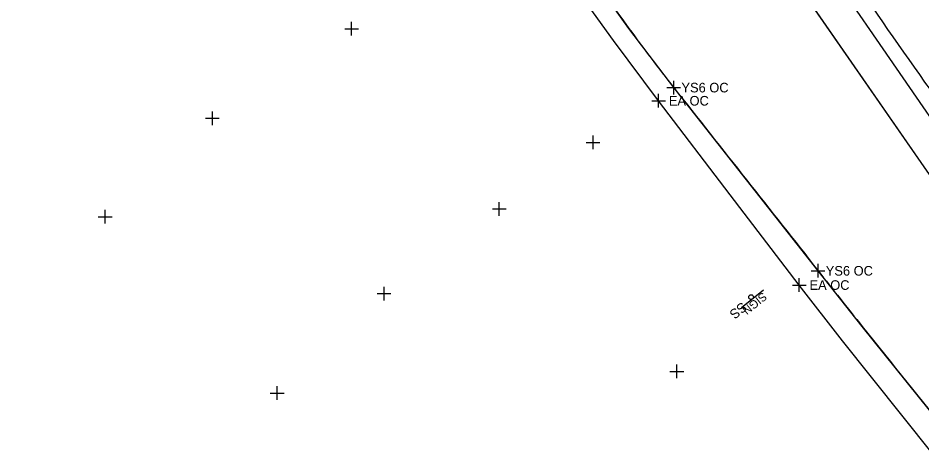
# Model space of a CAD drawing. Extents: x 1324236 to 1326110, y 459090 to 460782.
# Drawn here: x 1325451.1 to 1325582.8, y 459988.7 to 460050.8 of the extents above; entities that cross this region are included whole.
import ezdxf

# ---------------------------------------------------------------- set-up
doc = ezdxf.new("R2010")
doc.units = 0
for name, color, linetype in [('DR_X_Ditch', 7, 'Continuous'), ('DT_X_Contour_Minor', 7, 'Continuous'), ('DV_X_Property_Line', 7, 'Continuous'), ('LT_X_Poles', 7, 'Continuous'), ('PM_X_Edge_Line', 7, 'Continuous'), ('PM_X_Parking_Lot_Stall', 7, 'Continuous'), ('PV_X_Shoulder', 7, 'Continuous'), ('RW_X_CL', 7, 'Continuous')]:
    doc.layers.add(name, color=color, linetype=linetype)

msp = doc.modelspace()

# ---------------------------------------------------------------- linework, layer by layer
at = {"layer": 'DR_X_Ditch'}
for points in [[(1325392.48, 460306.14), (1325394.43, 460302.92), (1325394.43, 460302.92), (1325397.79, 460297.88), (1325401.32, 460292.96), (1325401.32, 460292.96), (1325418.59, 460267.6), (1325438.59, 460238.95), (1325456.84, 460212.47), (1325475.03, 460186.5), (1325492.65, 460160.91), (1325510.99, 460134.02), (1325529.23, 460107.34), (1325547.28, 460081.09), (1325565.79, 460054.08), (1325584.28, 460027.39)], [(1325587.07, 459989.64), (1325574.08, 460005.86), (1325574.08, 460005.86), (1325567.65, 460013.97), (1325567.65, 460013.97), (1325557.2, 460027.23), (1325557.2, 460027.23), (1325546.61, 460040.68), (1325546.61, 460040.68), (1325540.09, 460049.3), (1325540.09, 460049.3), (1325527.39, 460067.15), (1325527.39, 460067.15), (1325508.66, 460094.78), (1325491.31, 460120.25), (1325473.28, 460146.71), (1325455.4, 460172.68)]]:
    msp.add_lwpolyline(points, dxfattribs=at)
at = {"layer": 'DT_X_Contour_Minor'}
msp.add_line((1325559.71, 460011.16), (1325556.51, 460008.56), dxfattribs=at)
msp.add_circle((1325557.89, 460010.13), 0.344, dxfattribs=at)
at = {"layer": 'DV_X_Property_Line'}
for p, q in [((1325544.4, 460037.76), (1325544.4, 460039.76)), ((1325543.4, 460038.76), (1325545.4, 460038.76)), ((1325563.9, 460011.89), (1325565.9, 460011.89)), ((1325564.9, 460010.89), (1325564.9, 460012.89))]:
    msp.add_line(p, q, dxfattribs=at)
at = {"layer": 'LT_X_Poles'}
for points in [[(1325392.48, 460306.14), (1325394.43, 460302.92), (1325394.43, 460302.92), (1325397.79, 460297.88), (1325401.32, 460292.96), (1325401.32, 460292.96), (1325418.59, 460267.6), (1325438.59, 460238.95), (1325456.84, 460212.47), (1325475.03, 460186.5), (1325492.65, 460160.91), (1325510.99, 460134.02), (1325529.23, 460107.34), (1325547.28, 460081.09), (1325565.79, 460054.08), (1325584.28, 460027.39)], [(1325587.07, 459989.64), (1325574.08, 460005.86), (1325574.08, 460005.86), (1325567.65, 460013.97), (1325567.65, 460013.97), (1325557.2, 460027.23), (1325557.2, 460027.23), (1325546.61, 460040.68), (1325546.61, 460040.68), (1325540.09, 460049.3), (1325540.09, 460049.3), (1325527.39, 460067.15), (1325527.39, 460067.15), (1325508.66, 460094.78), (1325491.31, 460120.25), (1325473.28, 460146.71), (1325455.4, 460172.68)]]:
    msp.add_lwpolyline(points, dxfattribs=at)
at = {"layer": 'PM_X_Edge_Line'}
msp.add_line((1325565.79, 460054.08), (1325584.28, 460027.39), dxfattribs=at)
for centre, radius, start, end in [((1326460.74, 460717.66), 1137.68, 214.87524, 215.97833), ((1325764.53, 460212.24), 277.35, 215.9783, 218.2125), ((1376920.05, 500485.8), 65383.77, 218.2125439, 218.2275428), ((1375478.49, 499350.28), 63548.69, 218.227541, 218.2427549), ((1326880.42, 461048.61), 1671.48, 218.24275, 218.59782), ((1330829.75, 464201.07), 6724.72, 218.597815, 218.774832)]:
    msp.add_arc(centre, radius, start, end, dxfattribs=at)
at = {"layer": 'PM_X_Parking_Lot_Stall'}
msp.add_arc((1326187.06, 460471.05), 741.08, 213.87094, 215.52925, dxfattribs=at)
at = {"layer": 'PV_X_Shoulder'}
for points in [[(1325398.37, 460305.69), (1325405.2, 460296.15), (1325405.2, 460296.15), (1325422.82, 460270.39), (1325442.8, 460241.71), (1325461.19, 460215.15), (1325479.2, 460189.36), (1325496.93, 460163.57), (1325515.23, 460136.92), (1325533.46, 460110.33), (1325551.75, 460083.69), (1325569.83, 460056.87), (1325588.2, 460030.22)], [(1325584.27, 459987.36), (1325571.22, 460003.75), (1325571.22, 460003.75), (1325564.9, 460011.89), (1325564.9, 460011.89), (1325554.86, 460025.04), (1325554.86, 460025.04), (1325544.4, 460038.76), (1325544.4, 460038.76), (1325537.86, 460047.53), (1325537.86, 460047.53), (1325525.08, 460065.27), (1325525.08, 460065.27), (1325505.68, 460092.71), (1325488.21, 460118.14), (1325470.08, 460144.51), (1325452.3, 460170.59)]]:
    msp.add_lwpolyline(points, dxfattribs=at)
at = {"layer": 'RW_X_CL'}
for p, q in [((1325499.68, 460048.27), (1325499.68, 460050.27)), ((1325498.68, 460049.27), (1325500.68, 460049.27)), ((1325545.61, 460040.68), (1325547.61, 460040.68)), ((1325546.61, 460039.68), (1325546.61, 460041.68)), ((1325479.4, 460035.21), (1325479.4, 460037.21)), ((1325478.4, 460036.21), (1325480.4, 460036.21)), ((1325533.86, 460032.68), (1325535.86, 460032.68)), ((1325534.86, 460031.68), (1325534.86, 460033.68)), ((1325521.19, 460021.98), (1325521.19, 460023.98)), ((1325463.77, 460020.86), (1325463.77, 460022.86)), ((1325520.19, 460022.98), (1325522.19, 460022.98)), ((1325462.77, 460021.86), (1325464.77, 460021.86)), ((1325567.65, 460012.97), (1325567.65, 460014.97)), ((1325566.65, 460013.97), (1325568.65, 460013.97)), ((1325504.4, 460009.64), (1325504.4, 460011.64)), ((1325503.4, 460010.64), (1325505.4, 460010.64)), ((1325547.07, 459998.3), (1325547.07, 460000.3)), ((1325546.07, 459999.3), (1325548.07, 459999.3)), ((1325488.83, 459995.14), (1325488.83, 459997.14)), ((1325487.83, 459996.14), (1325489.83, 459996.14))]:
    msp.add_line(p, q, dxfattribs=at)

# ---------------------------------------------------------------- texts
at = {"layer": 'DT_X_Contour_Minor'}
for s, height, p in [('SIGN', 1.205, (1325559.57, 460010.91)), ('SS', 1.4, (1325556.55, 460009.49))]:
    msp.add_text(s, height=height, rotation=219.08, dxfattribs=at).set_placement(p)
at = {"layer": 'DV_X_Property_Line'}
for p in [(1325545.9, 460038.06), (1325566.4, 460011.19)]:
    msp.add_text('EA OC', height=1.4, dxfattribs=at).set_placement(p)
at = {"layer": 'RW_X_CL'}
for p in [(1325547.74, 460039.98), (1325568.77, 460013.27)]:
    msp.add_text('YS6 OC', height=1.4, dxfattribs=at).set_placement(p)

doc.saveas('drawing.dxf')
